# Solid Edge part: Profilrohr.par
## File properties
Username: bmolnar
Dokumentum tartalom típus: 0
Author: bmolnar
Last saved by: bmolnar
Revision: 86
Sűrűség: 0,000 kg/m^3
Pontosság: 0,990
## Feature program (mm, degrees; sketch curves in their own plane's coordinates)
base feature "unnamed BaseFeature 1"
thread "unnamed Thread 1"
thread "Menet_2"  ThreadDepth = 7.5 mm
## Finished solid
Body 1: solid body, 121 faces, 264 edges, 140 vertices.
  Faces by surface: plane 78, cylinder 29, cone 10, torus 4
  Edges by curve: line 188, circle 68, curve on surface 6, intersection 2
Bounding box of the edges (mm; curved faces can reach further): 65.000 x 70.000 x 89.500, from (-32.5, -32.5, 0) to (32.5, 37.5, 89.5).
Cylindrical faces by radius (mm): R1.375 x2, R3.4 x4, R4.283 x4, R5.5 x8, R25 x1, R25.9 x2, R26.1 x2, R27.6 x2, R43 x4
Conical faces (half-angle, radius in mm at the cone's reference point): 30 deg R25.325 x2, 30 deg R26.1887 x2, 45 deg R4.533 x2, 45 deg R26.25 x2, 45 deg R26.35 x2
Toroidal faces (ring radius, tube radius in mm): R27.4 r0.2 x4
Planar faces by outward normal: +x 9, +y 11, +z 8, -x 9, -y 9, -z 8, oblique 24
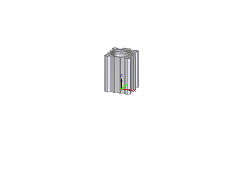
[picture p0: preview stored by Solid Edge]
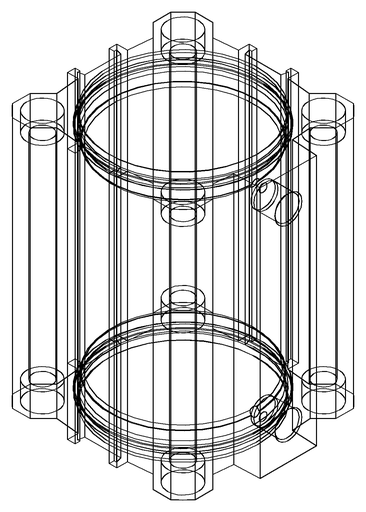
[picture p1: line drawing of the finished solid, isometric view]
